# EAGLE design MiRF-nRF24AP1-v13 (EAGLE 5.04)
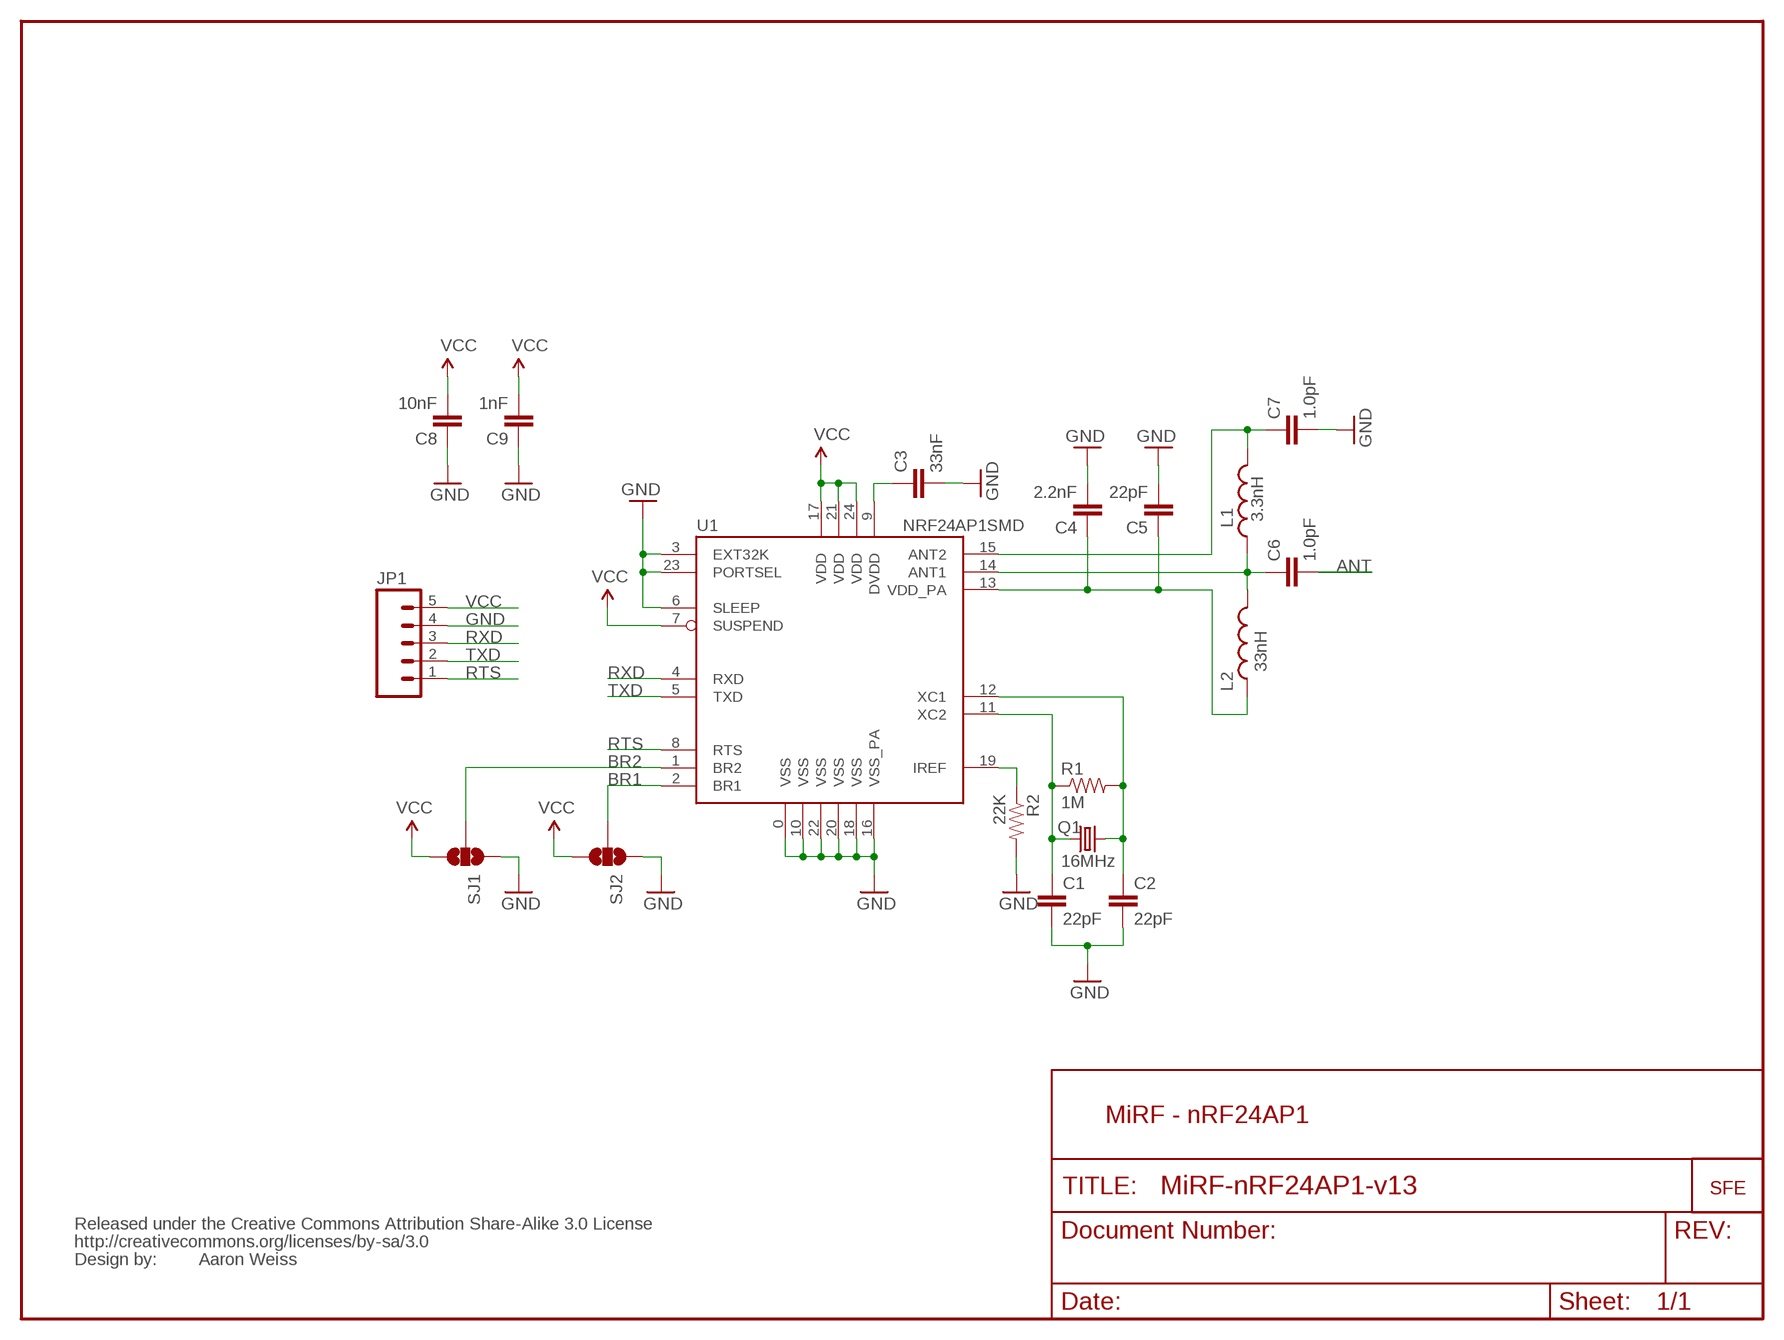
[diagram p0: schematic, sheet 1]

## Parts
C1  22pF  CAP0402-CAP  [0402-CAP]
C2  22pF  CAP0402-CAP  [0402-CAP]
C3  33nF  CAP0402-CAP  [0402-CAP]
C4  2.2nF  CAP0402-CAP  [0402-CAP]
C5  22pF  CAP0402-CAP  [0402-CAP]
C6  1.0pF  CAP0402-CAP  [0402-CAP]
C7  1.0pF  CAP0402-CAP  [0402-CAP]
C8  10nF  CAP0402-CAP  [0402-CAP]
C9  1nF  CAP0402-CAP  [0402-CAP]
JP1  M05PTH  [1X05]
L1  3.3nH  INDUCTOR0402  [C0402]
L2  33nH  INDUCTOR0402  [C0402]
Q1  16MHz  CRYSTAL5X3  [CRYSTAL-SMD-5X3]
R1  1M  RESISTOR0402-RES  [0402-RES]
R2  22K  RESISTOR0402-RES  [0402-RES]
SJ1  SOLDERJUMPER_2WAYS  [SJ_3]
SJ2  SOLDERJUMPER_2WAYS  [SJ_3]
U1  NRF24AP1SMD  [MLP-24]
U$1  CREATIVE_COMMONS  [CREATIVE_COMMONS]
U$2  LOGO-SFESK  [SFE-LOGO-FLAME]

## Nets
ANT: C6.2
BR1: SJ2.2 U1.2(BR1)
BR2: SJ1.2 U1.1(BR2)
GND: C1.2 C2.2 C3.2 C4.2 C5.2 C7.2 C8.1 C9.1 JP1.4 R2.2 SJ1.1 SJ2.1 U1.0(VSS) U1.3(EXT32K) U1.6(SLEEP) U1.10(VSS) U1.16(VSS_PA) U1.18(VSS) U1.20(VSS) U1.22(VSS) U1.23(PORTSEL)
N$1: C1.1 Q1.1 R1.1 U1.11(XC2)
N$2: C2.1 Q1.3 R1.2 U1.12(XC1)
N$3: C6.1 L1.1 L2.2 U1.14(ANT1)
N$4: R2.1 U1.19(IREF)
N$5: C3.1 U1.9(DVDD)
N$6: C7.1 L1.2 U1.15(ANT2)
N$7: C4.1 C5.1 L2.1 U1.13(VDD_PA)
RTS: JP1.1 U1.8(RTS)
RXD: JP1.3 U1.4(RXD)
TXD: JP1.2 U1.5(TXD)
VCC: C8.2 C9.2 JP1.5 SJ1.3 SJ2.3 U1.7(SUSPEND) U1.17(VDD) U1.21(VDD) U1.24(VDD)

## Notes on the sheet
- MiRF - nRF24AP1
- Aaron Weiss

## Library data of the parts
C1-C9 = SparkFun:CAP: Capacitor
JP1 = SparkFun:M05: Header 5 Standard 5-pin 0.1" header. Use with straight break away headers (SKU : PRT-00116), right angle break away headers (PRT-00553), swiss pins (PRT-00743), machine pins (PRT-00117), and female headers (PRT-00115). Molex polarized connector foot print use with SKU : PRT-08230 with associated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
L1 L2 = SparkFun:INDUCTOR: Inductors
Q1 = SparkFun:CRYSTAL: Crystals
R1 R2 = SparkFun:RESISTOR: Resistor
SJ1 SJ2 = SparkFun:SOLDERJUMPER_2WAY: Solder Jumper 2 way solder jumper
U1 = SparkFun:NRF24AP1: 2.4GHz ANT IC Nordic Semiconductor 2.4GHz transceiver that implements the ANT protocol.
U$1 = SparkFun:CREATIVE_COMMONS
U$2 = SparkFun:LOGO-SFE: Spark Fun Electronics PCB Logo

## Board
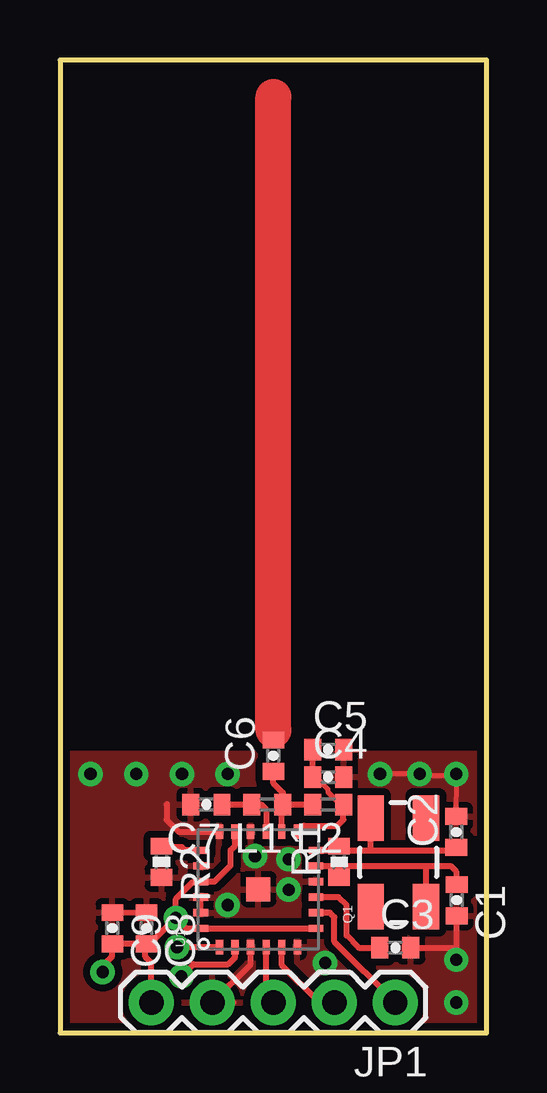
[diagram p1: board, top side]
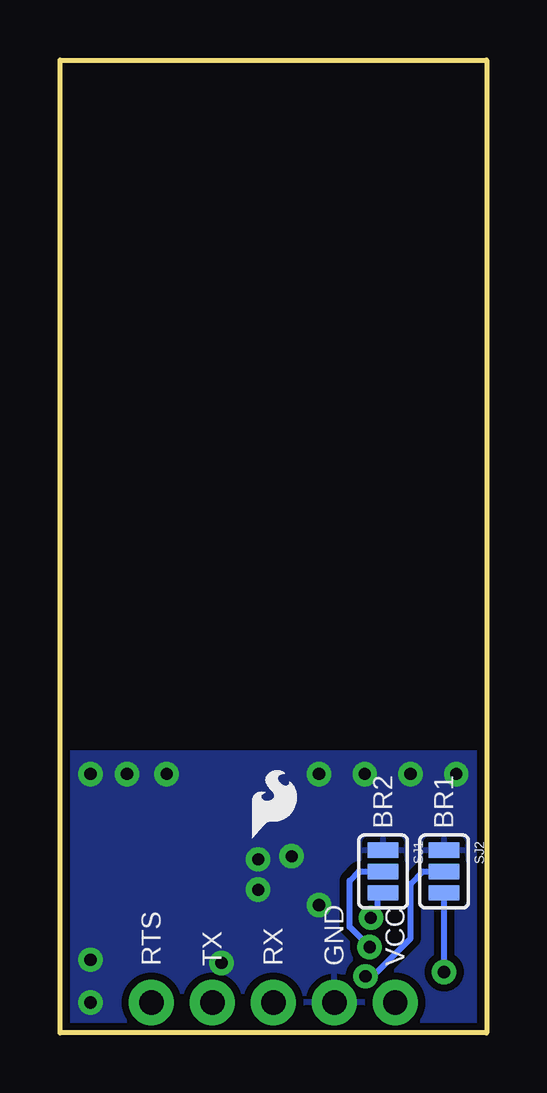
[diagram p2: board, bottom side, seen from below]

Size 17.78 x 40.56 mm. Coordinates in mm from the lower left corner, seen from the top.
Outline: 0,0 17.78,0 17.78,40.56 0,40.56 0,0
Copper layers (1*16): Top 0.035mm / dielectric 1.5mm / Bottom 0.035mm
Design rules "SparkFun": minimum track width 8mil, minimum drill 20mil, track to track 8mil, track to pad 8mil, pad to pad 8mil, via to via 8mil, smd to smd 8mil, copper to edge 9mil, drill to drill 8mil, minimum pad ring 12mil, minimum via ring 10mil, stop-mask expansion 4mil, vias tented up to drill 20mil, thermal gap 10mil

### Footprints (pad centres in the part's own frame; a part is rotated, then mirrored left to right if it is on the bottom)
0402-CAP = smd 0.7 x 0.9: 1 -0.65,0; 2 0.65,0
1X05 = drill 1.016 pad 1.88 round: 1 0,0; 2 2.54,0; 3 5.08,0; 4 7.62,0; 5 10.16,0
C0402 = smd 0.7 x 0.9: 1 -0.65,0; 2 0.65,0
CRYSTAL-SMD-5X3 = smd 1.9 x 1.1: 1 -1.85,-1.15; 2 1.85,-1.15; 3 1.85,1.15; 4 -1.85,1.15
0402-RES = smd 0.7 x 0.9: 1 -0.65,0; 2 0.65,0
SJ_3 = smd 0.635 x 1.27: 1 -0.889,0; 2 0,0; 3 0.889,0
MLP-24 = smd 1 x 1: 0 0,0 | smd 0.61 x 0.305: 1 -2.401,1.625; 2 -2.401,0.975; 3 -2.401,0.325; 4 -2.401,-0.325; 5 -2.401,-0.975; 6 -2.401,-1.625; 13 2.401,-1.625; 14 2.401,-0.975; 15 2.401,-0.325; 16 2.401,0.325; 17 2.401,0.975; 18 2.401,1.625 | smd 0.305 x 0.61: 7 -1.625,-2.401; 8 -0.975,-2.401; 9 -0.325,-2.401; 10 0.325,-2.401; 11 0.975,-2.401; 12 1.625,-2.401; 19 1.625,2.401; 20 0.975,2.401; 21 0.325,2.401; 22 -0.325,2.401; 23 -0.975,2.401; 24 -1.625,2.401

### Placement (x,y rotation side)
C1  16.53,5.54 270 top
C2  16.51,8.38 90 top
C3  13.97,3.56 0 top
C4  11.18,10.67 0 top
C5  11.18,11.81 0 top
C6  8.89,11.56 90 top
C7  6.1,9.53 180 top
C8  3.61,4.37 270 top
C9  2.18,4.37 270 top
JP1  13.97,1.27 180 top
L1  8.64,9.53 180 top
L2  11.18,9.53 180 top
Q1  14.1,7.11 90 top
R1  11.63,7.14 90 top
R2  4.23,7.14 270 top
SJ1  4.32,6.73 270 bottom
SJ2  1.78,6.73 270 bottom
U1  8.27,5.99 90 top
U$1  not placed on the board
U$2  9.78,8.13 0 bottom

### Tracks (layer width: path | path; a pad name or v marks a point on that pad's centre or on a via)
BR1  (via drill 0.51)
  Top 0.254: U1.2 7.29,3.15 7.01,2.87 5.56,2.87 v5.05,2.36
  Bottom 0.254: SJ2.2 2.67,6.73 3.17,6.22 3.17,3.94 4.75,2.36 v5.05,2.36
BR2  (via drill 0.51)
  Top 0.254: U1.1 5.62,3.59 v4.88,3.58
  Bottom 0.254: SJ1.2 5.33,6.73 5.71,6.35 5.71,4.42 v4.88,3.58
GND  (via drill 0.51)
  Top 0.203: C1.2 | JP1.4 6.35,1.4 | C8.1 3.56,5.08 3.5,5.02 C9.1 | U1.23 U1.22 5.97,5.71 | C2.2 16.53,10.65 16.47,10.71 v16.51,10.79 16.51,10.72 15.04,10.72 14.99,10.67 v14.99,10.79 v13.34,10.79 13.21,10.67
  Top 0.254: C1.2 16.53,3.45 v16.51,3.05 | v16.51,3.05 16.46,3.48 | U1.18 4.95,8.39 4.45,8.89 4.45,9.53 4.46,9.54 | v16.51,3.05 16.51,3.56 C3.2 | 7.24,1.27 JP1.4 7.94,2.86 U1.3
  other vias: 16.51,1.27 1.27,10.79 6.99,10.79 5.08,10.79 9.53,5.97 9.53,7.24 8.13,7.37 3.17,10.79 11.05,2.92 6.99,5.33
  pour Bottom (isolate 0.305): 0,11.68 17.78,11.68 17.78,0 0,0
  pour Top (isolate 0.305): 0,11.68 17.78,11.68 17.78,0 0,0
N$1
  Top 0.254: U1.11 11.56,6.96 | 11.56,6.96 15.24,6.96 | 15.24,6.96 16.28,6.96 16.51,6.73 16.51,6.22 16.53,6.2 C1.1 | 11.56,6.96 11.56,6.99 11.63,6.91 R1.1 | 15.24,6.96 15.24,6.86 15.25,6.85 Q1.1
N$2
  Top 0.254: C2.1 16.51,7.75 16.38,7.61 12.95,7.61 | U1.12 11.56,7.61 | 11.56,7.61 12.95,7.61 | 12.95,7.61 12.95,7.62 12.95,7.63 Q1.3 | 11.56,7.61 11.56,7.62 11.63,7.69 R1.2
N$3
  Top 0.254: L1.1 9.27,9.53 9.24,9.5 U1.14 | L2.2 10.54,9.53 L1.1 | C6.1 8.89,10.41 9.29,10.02 L1.1
N$4
  Top 0.254: U1.19 5.21,7.61 5.08,7.75 4.19,7.75 R2.1
N$5
  Top 0.254: U1.9 11.61,5.66 11.94,5.33 11.94,4.06 12.45,3.56 C3.1 13.34,3.56
N$6
  Top 0.254: C7.1 L1.2 8.38,9.53 8.59,9.31 U1.15
N$7
  Top 0.203: L2.1 11.68,9.53 11.18,10.03 11.18,10.16 10.67,10.67 C4.1
  Top 0.254: C5.1 10.53,10.68 10.54,10.67 C4.1 | U1.13 9.91,8.39 10.16,8.64 11.56,8.64 11.81,8.89 11.81,9.4 11.83,9.41 L2.1
N$8
  Top 1.5: 8.89,12.62 8.89,39.02
RTS
  Top 0.254: U1.8 11.24,5.01 11.43,4.83 11.43,3.81 JP1.1
RXD
  Top 0.254: U1.4 8.59,1.57 JP1.3
TXD
  Top 0.254: U1.5 9.24,2.82 10.79,1.27 JP1.2
VCC  (via drill 0.51)
  Top 0.203: C8.2 3.65,3.72 | U1.21 | U1.21
  Top 0.254: v1.78,2.54 1.78,2.79 2.16,3.17 2.16,3.68 2.18,3.71 C9.2 3.52,3.72 3.56,3.68 | U1.24 5.87,4.34 5.89,4.36 | 5.89,4.36 U1.7 | U1.21 6.44,6.31 7.11,6.99 7.11,7.62 7.29,7.8 U1.17 | JP1.5 3.81,2.92 3.56,3.17 3.56,3.68 | 3.56,3.68 3.59,3.72 C8.2 | U1.21 5.54,6.3 4.83,5.59 v4.83,4.8 | 5.89,4.36 5.26,4.36 v4.83,4.8 | 3.65,3.72 3.75,3.72 v4.83,4.8
  Bottom 0.203: SJ1.3 4.47,5.84 4.55,5.77
  Bottom 0.254: v1.78,2.54 SJ2.3 | 4.55,5.77 4.55,5.08 v4.83,4.8

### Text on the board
bPlace: BR1 | BR2 | VCC | GND | RX | TX | RTS
tValues: DNP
